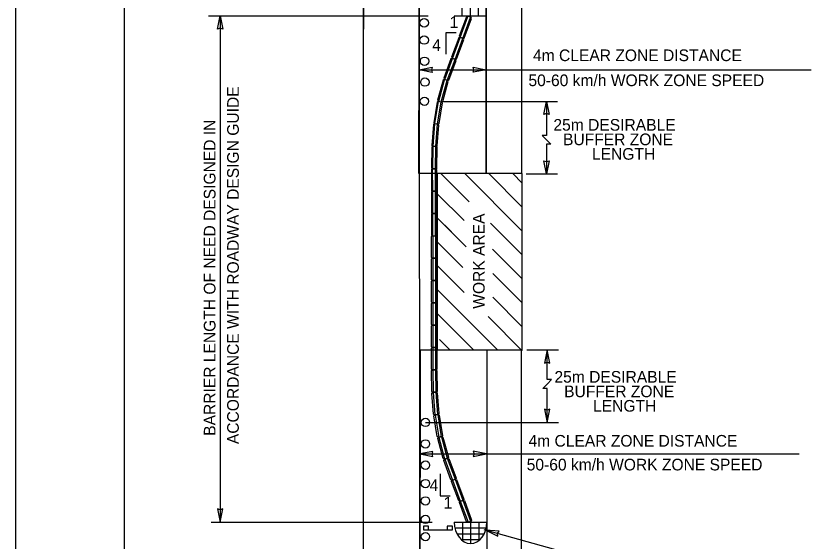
# Model space of a CAD drawing. Extents: x 2427 to 2645, y -255 to 24.
# Drawn here: x 2429 to 2565.3, y -162 to -71.9 of the extents above; entities that cross this region are included whole.
import ezdxf

# ---------------------------------------------------------------- set-up
doc = ezdxf.new("R2010")
doc.units = 0
for name, color, linetype in [('Level 10', 7, 'Continuous'), ('Level 17', 7, 'Continuous'), ('Level 20', 7, 'Continuous'), ('Level 22', 7, 'Continuous'), ('Level 4', 7, 'Continuous'), ('Level 44', 7, 'Continuous'), ('Level 5', 7, 'Continuous'), ('Level 60', 7, 'Continuous')]:
    doc.layers.add(name, color=color, linetype=linetype)

# ---------------------------------------------------------------- blocks, each defined once
blk = doc.blocks.new('arrow')
at = {"layer": 'Level 60'}
blk.add_lwpolyline([(0.6, 0.12), (0, 0), (0.6, -0.12), (0.56, 0)], close=True, dxfattribs=at)
blk = doc.blocks.new('BREAK')
at = {"layer": 'Level 20'}
blk.add_lwpolyline([(-12.499, 0), (-2.5, 0), (-2.5, 2.5), (0, 0), (2.501, -2.501), (2.501, 0), (12.501, 0)], dxfattribs=at)

msp = doc.modelspace()

# ---------------------------------------------------------------- linework, layer by layer
at = {"layer": 'Level 10'}
for p, q in [((2488.59, 3.9), (2488.59, -74.14)), ((2515.69, 3.9), (2515.69, -98.92)), ((2488.6, -172.56), (2488.6, -48.35)), ((2498.24, -172.68), (2498.19, -55.44)), ((2515.68, -98.92), (2501.28, -98.92)), ((2501.28, -129.21), (2501.28, -98.92)), ((2506.68, -103.74), (2501.86, -98.92)), ((2515.81, -108.76), (2505.96, -98.92)), ((2515.81, -104.66), (2510.07, -98.92)), ((2515.81, -100.55), (2514.17, -98.92)), ((2515.81, -129.21), (2515.81, -98.92)), ((2505.81, -106.98), (2501.28, -102.45)), ((2506.17, -111.45), (2501.28, -106.56)), ((2503.64, -108.91), (2501.29, -106.56)), ((2515.81, -112.87), (2510.35, -107.41)), ((2505.63, -115), (2501.28, -110.65)), ((2515.81, -116.97), (2510.71, -111.88)), ((2505.81, -119.29), (2501.28, -114.76)), ((2515.81, -121.08), (2510.75, -116.03)), ((2511.62, -129.21), (2501.28, -118.87)), ((2515.81, -125.18), (2510.73, -120.11)), ((2507.51, -129.21), (2501.28, -122.97)), ((2515.81, -129.29), (2509.97, -123.45)), ((2503.41, -129.21), (2501.59, -127.39)), ((2515.81, -129.21), (2501.28, -129.21)), ((2515.69, -240.54), (2515.69, -129.21)), ((2488.6, -240.54), (2488.6, -148.86))]:
    msp.add_line(p, q, dxfattribs=at)
for points in [[(2501.97, 3.9), (2513.52, 3.9), (2513.4, -42.82), (2509.61, -56.11), (2509.63, -98.92), (2498.08, -98.91), (2498.19, -55.44)], [(2509.8, -217.04), (2509.89, -240.54), (2521.44, -240.54), (2521.44, -213.34), (2509.79, -172.46), (2509.77, -129.21), (2498.32, -129.19), (2498.24, -172.95), (2498.38, -174.49)]]:
    msp.add_lwpolyline(points, dxfattribs=at)
for centre in [(2498.98, -73.05), (2498.98, -76.02), (2499.04, -79.64), (2499.11, -83.22), (2499.02, -86.51), (2499.2, -141.6), (2499.2, -145.28), (2499.2, -148.93), (2499.2, -152.09), (2499.2, -155.06), (2499.2, -158.23), (2499.2, -161.19)]:
    msp.add_circle(centre, 0.718, dxfattribs=at)
at = {"layer": 'Level 17'}
msp.add_line((2428.98, -254.99), (2428.98, 24.01), dxfattribs=at)
at = {"layer": 'Level 22'}
msp.add_line((2447.52, 12.32), (2447.52, -244.18), dxfattribs=at)
at = {"layer": 'Level 4'}
for p, q in [((2505.52, -71.86), (2505.52, -68.67)), ((2506.92, -71.86), (2506.92, -68.18)), ((2508.32, -71.86), (2508.32, -68.67)), ((2504.11, -71.86), (2509.72, -71.86)), ((2506.23, -72.01), (2504.99, -75.36)), ((2505.16, -75.56), (2506.49, -71.96)), ((2505.59, -75.72), (2506.92, -72.12)), ((2506.4, -71.93), (2506.23, -72.01)), ((2507.02, -72.16), (2506.4, -71.93)), ((2507.1, -72.33), (2507.02, -72.16)), ((2505.86, -75.68), (2507.1, -72.33)), ((2504.91, -75.61), (2503.67, -78.96)), ((2503.84, -79.16), (2505.17, -75.57)), ((2504.27, -79.32), (2505.6, -75.72)), ((2504.54, -79.28), (2505.78, -75.93)), ((2505.08, -75.53), (2504.91, -75.61)), ((2504.99, -75.36), (2505.07, -75.53)), ((2505.07, -75.53), (2505.69, -75.76)), ((2505.7, -75.76), (2505.08, -75.53)), ((2505.86, -75.68), (2505.69, -75.76)), ((2505.78, -75.93), (2505.7, -75.76)), ((2503.67, -78.96), (2503.75, -79.13)), ((2503.57, -79.21), (2502.33, -82.56)), ((2502.51, -82.76), (2503.83, -79.16)), ((2502.94, -82.92), (2504.27, -79.32)), ((2503.2, -82.88), (2504.44, -79.53)), ((2503.74, -79.13), (2503.57, -79.21)), ((2504.36, -79.36), (2503.74, -79.13)), ((2503.75, -79.13), (2504.37, -79.36)), ((2504.44, -79.53), (2504.36, -79.36)), ((2504.54, -79.28), (2504.37, -79.36)), ((2502.23, -82.87), (2501.29, -86.32)), ((2501.48, -86.51), (2502.49, -82.81)), ((2501.92, -86.63), (2502.93, -82.93)), ((2502.18, -86.56), (2503.12, -83.12)), ((2502.39, -82.78), (2502.23, -82.87)), ((2502.33, -82.56), (2502.41, -82.73)), ((2503.03, -82.96), (2502.39, -82.78)), ((2502.41, -82.73), (2503.03, -82.96)), ((2503.2, -82.88), (2503.03, -82.96)), ((2503.12, -83.12), (2503.03, -82.96)), ((2501.21, -86.65), (2500.63, -90.18)), ((2500.83, -90.34), (2501.46, -86.56)), ((2501.36, -86.54), (2501.21, -86.65)), ((2501.29, -86.32), (2501.38, -86.48)), ((2501.29, -90.42), (2501.91, -86.63)), ((2502.02, -86.65), (2501.36, -86.54)), ((2501.38, -86.48), (2502.02, -86.66)), ((2501.54, -90.33), (2502.12, -86.8)), ((2502.18, -86.56), (2502.02, -86.66)), ((2502.12, -86.8), (2502.02, -86.65)), ((2500.57, -90.5), (2500.28, -94.07)), ((2500.5, -94.22), (2500.81, -90.39)), ((2500.72, -90.38), (2500.57, -90.5)), ((2500.63, -90.18), (2500.74, -90.33)), ((2501.38, -90.44), (2500.72, -90.38)), ((2500.74, -90.33), (2501.39, -90.44)), ((2500.96, -94.26), (2501.27, -90.43)), ((2501.2, -94.14), (2501.5, -90.58)), ((2501.5, -90.58), (2501.38, -90.44)), ((2501.54, -90.33), (2501.39, -90.44)), ((2500.28, -94.07), (2500.4, -94.21)), ((2500.27, -94.37), (2500.21, -97.95)), ((2500.4, -94.25), (2500.27, -94.37)), ((2500.4, -94.21), (2501.06, -94.26)), ((2501.06, -94.26), (2500.4, -94.25)), ((2500.44, -98.08), (2500.5, -94.25)), ((2500.9, -98.09), (2500.96, -94.25)), ((2501.2, -94.14), (2501.06, -94.26)), ((2501.19, -94.39), (2501.06, -94.26)), ((2501.13, -97.97), (2501.19, -94.39)), ((2500.21, -97.95), (2500.34, -98.08)), ((2500.34, -98.09), (2500.21, -98.22)), ((2500.34, -98.08), (2501, -98.09)), ((2501, -98.09), (2500.34, -98.09)), ((2500.44, -101.92), (2500.43, -98.09)), ((2500.9, -101.92), (2500.9, -98.08)), ((2501.13, -97.97), (2501, -98.09)), ((2501.13, -98.21), (2501, -98.09)), ((2500.21, -98.22), (2500.21, -101.79)), ((2501.13, -101.79), (2501.13, -98.21)), ((2500.21, -101.79), (2500.34, -101.92)), ((2500.34, -101.92), (2500.21, -102.05)), ((2500.21, -102.05), (2500.21, -105.63)), ((2501, -101.92), (2500.34, -101.92)), ((2500.34, -101.92), (2501, -101.92)), ((2500.44, -105.76), (2500.44, -101.92)), ((2500.9, -105.76), (2500.9, -101.92)), ((2501.13, -101.79), (2501, -101.92)), ((2501.13, -102.05), (2501, -101.92)), ((2501.14, -105.63), (2501.13, -102.05)), ((2500.21, -105.63), (2500.35, -105.76)), ((2500.34, -105.75), (2500.21, -105.88)), ((2500.21, -105.88), (2500.21, -109.46)), ((2501, -105.75), (2500.34, -105.75)), ((2500.35, -105.76), (2501.01, -105.76)), ((2500.44, -109.59), (2500.44, -105.75)), ((2500.9, -109.59), (2500.9, -105.75)), ((2501.13, -105.88), (2501, -105.75)), ((2501.14, -105.63), (2501.01, -105.76)), ((2501.14, -109.46), (2501.13, -105.88)), ((2500.21, -109.46), (2500.35, -109.59)), ((2500.21, -109.73), (2500.34, -109.6)), ((2500.21, -113.3), (2500.21, -109.73)), ((2500.34, -109.6), (2501, -109.6)), ((2500.35, -109.59), (2501.01, -109.59)), ((2500.44, -109.6), (2500.44, -113.43)), ((2500.9, -109.59), (2500.9, -113.43)), ((2501.14, -109.73), (2501, -109.6)), ((2501.14, -109.46), (2501.01, -109.59)), ((2501.14, -109.73), (2501.13, -113.3)), ((2500.34, -113.43), (2500.21, -113.3)), ((2500.21, -113.56), (2500.34, -113.43)), ((2500.21, -117.13), (2500.21, -113.56)), ((2501, -113.43), (2500.34, -113.43)), ((2500.34, -113.43), (2501, -113.43)), ((2500.44, -113.43), (2500.44, -117.26)), ((2500.9, -113.42), (2500.9, -117.26)), ((2501.13, -113.3), (2501, -113.43)), ((2501.14, -113.56), (2501, -113.43)), ((2501.14, -113.56), (2501.13, -117.13)), ((2500.34, -117.26), (2500.21, -117.13)), ((2500.21, -117.39), (2500.34, -117.26)), ((2500.34, -117.26), (2501, -117.26)), ((2500.44, -117.26), (2500.44, -121.09)), ((2500.9, -117.25), (2500.9, -121.09)), ((2501.13, -117.13), (2501, -117.26)), ((2501.14, -117.39), (2501, -117.26)), ((2500.21, -120.96), (2500.21, -117.39)), ((2501, -117.26), (2500.34, -117.26)), ((2501.14, -117.39), (2501.13, -120.96)), ((2500.34, -121.09), (2500.21, -120.96)), ((2500.21, -121.22), (2500.34, -121.09)), ((2500.21, -124.79), (2500.21, -121.22)), ((2501, -121.09), (2500.34, -121.09)), ((2500.34, -121.09), (2501, -121.09)), ((2500.44, -121.09), (2500.44, -124.92)), ((2500.9, -121.08), (2500.9, -124.92)), ((2501.13, -120.96), (2501, -121.09)), ((2501.14, -121.22), (2501, -121.09)), ((2501.14, -121.22), (2501.13, -124.79)), ((2500.34, -124.92), (2500.21, -124.79)), ((2500.21, -125.05), (2500.34, -124.92)), ((2500.21, -128.62), (2500.21, -125.05)), ((2501, -124.92), (2500.34, -124.92)), ((2500.34, -124.92), (2501, -124.92)), ((2500.44, -124.92), (2500.44, -128.75)), ((2500.9, -124.92), (2500.9, -128.75)), ((2501.13, -124.79), (2501, -124.92)), ((2501.14, -125.05), (2501, -124.92)), ((2501.14, -125.05), (2501.13, -128.62)), ((2500.34, -128.75), (2500.21, -128.62)), ((2500.21, -128.88), (2500.34, -128.75)), ((2500.21, -132.45), (2500.21, -128.88)), ((2501, -128.75), (2500.34, -128.75)), ((2500.34, -128.75), (2501, -128.75)), ((2500.44, -128.75), (2500.44, -132.58)), ((2500.9, -128.75), (2500.9, -132.58)), ((2501.13, -128.62), (2501, -128.75)), ((2501.14, -128.88), (2501, -128.75)), ((2501.14, -128.88), (2501.13, -132.45)), ((2500.34, -132.58), (2500.21, -132.45)), ((2500.21, -132.72), (2500.34, -132.59)), ((2500.28, -136.3), (2500.21, -132.72)), ((2501, -132.58), (2500.34, -132.58)), ((2500.34, -132.59), (2501, -132.58)), ((2500.44, -132.59), (2500.51, -136.42)), ((2500.9, -132.58), (2500.97, -136.42)), ((2501.13, -132.45), (2501, -132.58)), ((2501.14, -132.71), (2501, -132.58)), ((2501.14, -132.71), (2501.2, -136.28)), ((2500.41, -136.43), (2500.28, -136.3)), ((2501.2, -136.28), (2501.07, -136.41)), ((2500.29, -136.61), (2500.41, -136.46)), ((2500.58, -140.17), (2500.29, -136.61)), ((2500.41, -136.46), (2501.07, -136.41)), ((2501.07, -136.41), (2500.41, -136.43)), ((2500.51, -136.46), (2500.82, -140.28)), ((2500.97, -136.42), (2501.28, -140.24)), ((2501.21, -136.53), (2501.07, -136.41)), ((2501.21, -136.53), (2501.5, -140.09)), ((2500.72, -140.29), (2500.58, -140.17)), ((2500.63, -140.49), (2500.74, -140.34)), ((2501.38, -140.23), (2500.72, -140.29)), ((2500.74, -140.34), (2501.4, -140.24)), ((2500.84, -140.33), (2501.47, -144.11)), ((2501.3, -140.25), (2501.92, -144.04)), ((2501.5, -140.09), (2501.38, -140.23)), ((2501.55, -140.34), (2501.4, -140.24)), ((2501.55, -140.34), (2502.13, -143.87)), ((2501.22, -144.02), (2500.63, -140.49)), ((2501.37, -144.13), (2501.22, -144.02)), ((2501.3, -144.35), (2501.39, -144.19)), ((2502.24, -147.8), (2501.3, -144.35)), ((2502.02, -144.02), (2501.37, -144.13)), ((2501.39, -144.19), (2502.03, -144.02)), ((2501.49, -144.16), (2502.49, -147.86)), ((2501.93, -144.04), (2502.94, -147.75)), ((2502.13, -143.87), (2502.02, -144.02)), ((2502.19, -144.11), (2502.03, -144.02)), ((2502.19, -144.11), (2503.13, -147.56)), ((2502.4, -147.89), (2502.24, -147.8)), ((2502.34, -148.11), (2502.42, -147.95)), ((2503.58, -151.47), (2502.34, -148.11)), ((2503.04, -147.72), (2502.4, -147.89)), ((2502.42, -147.95), (2503.04, -147.72)), ((2502.51, -147.91), (2503.84, -151.51)), ((2502.94, -147.75), (2504.27, -151.35)), ((2503.13, -147.56), (2503.04, -147.72)), ((2503.21, -147.79), (2503.04, -147.72)), ((2503.21, -147.79), (2504.45, -151.15)), ((2504.37, -151.32), (2503.75, -151.54)), ((2503.75, -151.54), (2504.38, -151.32)), ((2504.45, -151.15), (2504.37, -151.32)), ((2504.54, -151.39), (2504.38, -151.32)), ((2503.75, -151.54), (2503.58, -151.47)), ((2503.67, -151.71), (2503.75, -151.54)), ((2504.92, -155.06), (2503.67, -151.71)), ((2503.85, -151.51), (2505.18, -155.11)), ((2504.28, -151.35), (2505.61, -154.95)), ((2504.54, -151.39), (2505.78, -154.74)), ((2505.09, -155.14), (2504.92, -155.06)), ((2505.01, -155.31), (2505.09, -155.14)), ((2506.25, -158.66), (2505.01, -155.31)), ((2505.71, -154.91), (2505.09, -155.14)), ((2505.09, -155.14), (2505.71, -154.91)), ((2505.18, -155.11), (2506.51, -158.71)), ((2505.61, -154.95), (2506.94, -158.55)), ((2505.78, -154.74), (2505.71, -154.91)), ((2505.88, -154.99), (2505.71, -154.91)), ((2505.88, -154.99), (2507.11, -158.34)), ((2504.13, -158.69), (2509.74, -158.69)), ((2505.54, -158.69), (2505.54, -161.88)), ((2506.42, -158.74), (2506.25, -158.66)), ((2507.04, -158.51), (2506.42, -158.74)), ((2506.94, -158.69), (2506.94, -162.38)), ((2507.11, -158.34), (2507.04, -158.51)), ((2508.34, -158.69), (2508.34, -161.88)), ((2504.24, -159.69), (2509.64, -159.69)), ((2504.58, -160.69), (2509.29, -160.69)), ((2505.31, -161.69), (2508.56, -161.69))]:
    msp.add_line(p, q, dxfattribs=at)
msp.add_ellipse((2506.94, -158.68), major_axis=(0, -3.7), ratio=0.758621, start_param=4.716532, end_param=7.849839, dxfattribs=at)
at = {"layer": 'Level 5'}
for p, q in [((2509.63, -98.92), (2509.61, -56.11)), ((2462.02, -71.86), (2499.64, -71.86)), ((2464.02, -71.86), (2464.02, -158.69)), ((2502.76, -78.45), (2502.76, -74.69)), ((2502.76, -74.69), (2504.47, -74.69)), ((2498.12, -81.12), (2565.32, -81.12)), ((2502.31, -86.53), (2521.85, -86.53)), ((2519.95, -86.53), (2519.95, -91.34)), ((2519.95, -95.12), (2519.95, -98.95)), ((2516.46, -98.95), (2521.85, -98.95)), ((2509.79, -172.46), (2509.77, -129.21)), ((2516.59, -129.17), (2521.99, -129.17)), ((2520.08, -133), (2520.08, -129.17)), ((2520.08, -141.6), (2520.08, -136.79)), ((2499.2, -141.6), (2521.99, -141.6)), ((2498.23, -147.01), (2563.3, -147.01)), ((2501.75, -150.43), (2501.75, -154.19)), ((2501.75, -154.19), (2503.46, -154.19)), ((2462.44, -158.69), (2500.37, -158.69)), ((2499.75, -159.39), (2498.88, -159.39)), ((2498.88, -159.39), (2498.88, -160)), ((2499.75, -160), (2499.75, -159.39)), ((2503.81, -159.39), (2502.93, -159.39)), ((2502.93, -159.39), (2502.93, -160)), ((2503.81, -160), (2503.81, -159.39)), ((2498.88, -160), (2503.81, -160))]:
    msp.add_line(p, q, dxfattribs=at)
msp.add_lwpolyline([(2529.3, -164.45), (2525.07, -164.45), (2509.28, -160.01)], dxfattribs=at)

# ---------------------------------------------------------------- block references
at = {"layer": 'Level 10', "xscale": 3.75}
for p, yscale, rotation in [((2464.02, -71.86), -3.75, -90), ((2519.95, -86.53), -3.75, -90), ((2519.95, -98.95), -3.75, 90), ((2520.08, -129.17), 3.75, -90), ((2520.08, -141.6), 3.75, 90), ((2464.02, -158.69), 3.75, 90)]:
    msp.add_blockref('arrow', p, dxfattribs=dict(at, yscale=yscale, rotation=rotation))
at = {"layer": 'Level 5', "xscale": 3.75}
for p, yscale in [((2498.12, -81.12), -3.75), ((2498.23, -147.01), 3.75)]:
    msp.add_blockref('arrow', p, dxfattribs=dict(at, yscale=yscale))
at = {"layer": 'Level 5'}
for name, p, xscale, yscale, rotation in [('arrow', (2509.61, -81.09), 3.75, -3.75, 180), ('BREAK', (2519.94, -93.12), 0.30000000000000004, -0.30000000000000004, -90), ('BREAK', (2520.07, -135.01), 0.30000000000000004, 0.30000000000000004, 90), ('arrow', (2509.64, -147), 3.75, 3.75, 180), ('arrow', (2509.54, -160.08), 3.750000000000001, 3.7500000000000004, -15.697792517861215)]:
    msp.add_blockref(name, p, dxfattribs=dict(at, xscale=xscale, yscale=yscale, rotation=rotation))

# ---------------------------------------------------------------- texts
at = {"layer": 'Level 10'}
msp.add_text('WORK AREA', height=2, rotation=90, dxfattribs=at).set_placement((2509.35, -122.1))
at = {"layer": 'Level 44'}
for s, rotation, p in [('ACCORDANCE WITH ROADWAY DESIGN GUIDE', 90, (2467.2, -145.32)), ('BARRIER LENGTH OF NEED DESIGNED IN', 90, (2463.2, -143.89)), ('25m DESIRABLE', 360, (2521.32, -134.78)), ('BUFFER ZONE', 360, (2522.98, -137.27)), ('LENGTH', 360, (2527.94, -139.75))]:
    msp.add_text(s, height=2, rotation=rotation, dxfattribs=at).set_placement(p)
for s, p in [('25m DESIRABLE', (2521.14, -91.55)), ('BUFFER ZONE', (2522.79, -94.04)), ('LENGTH', (2527.75, -96.53))]:
    msp.add_text(s, height=2, dxfattribs=at).set_placement(p)
at = {"layer": 'Level 5'}
for s, p in [('1', (2503.34, -73.92)), ('4', (2500.36, -77.86)), ('50-60 km/h WORK ZONE SPEED', (2516.86, -83.91)), ('50-60 km/h WORK ZONE SPEED', (2516.56, -149.83)), ('4', (2499.91, -153.37)), ('1', (2502.31, -156.37))]:
    msp.add_text(s, height=2, dxfattribs=at).set_placement(p)
for p in [(2517.64, -79.62), (2516.87, -145.75)]:
    msp.add_text('4m CLEAR ZONE DISTANCE', height=2, rotation=360, dxfattribs=at).set_placement(p)

doc.saveas('drawing.dxf')
